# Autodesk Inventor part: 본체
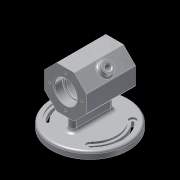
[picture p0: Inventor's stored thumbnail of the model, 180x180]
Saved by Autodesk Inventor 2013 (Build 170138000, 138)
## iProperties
Created: 2017-06
Part Number: 본체
Material: 알루미늄 6061
Document SubType Name: Modeling
Designer: Administrator
Density: 2.71 g/cm^3
Mass: 562.521 g
Surface Area: 565.55 cm^2
Volume: 207.572 cm^3
Author: Administrator
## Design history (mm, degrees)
sketch "스케치1"
  geometry: L1 (12.426, 30)-(30, 12.426); L2 (30, 12.426)-(30, -12.426); L3 (30, -12.426)-(12.426, -30); L4 (12.426, -30)-(-12.426, -30); L5 (-12.426, -30)-(-30, -12.426); L6 (-30, -12.426)-(-30, 12.426); L7 (-30, 12.426)-(-12.426, 30); L8 (-12.426, 30)-(12.426, 30); C1 r 30 at (0, 0); 2 further points
  constraints: 16 end point, 2 coincident, 1 centre point, 1 horizontal, 1 tangent, 17 other
  dimensions: "d2" = 60 diameter of C1
extrude "돌출1" new body sketch "스케치1" distance "d0" = 70; taper "d1" = 0 deg
sketch "스케치2" dims "d4" = 46
  geometry: 3 further points
  constraints: 2 vertical alignment, 1 coincident, 2 other
hole "구멍1" sketch "스케치2" at (0, 23) diameter "d6" = 3.242; stored, may be unused: countersink angle "d10" = 90 deg, drill point angle "d12" = 118 deg; dims "d7" = 8, "d8" = 4, "d9" = 2, "d11" = 10
sketch "스케치3"
  geometry: L1 (0, 0)-(70, 0); L2 (0, 0)-(0, 16); L3 (0, 16)-(12, 16); L4 (12, 16)-(12, 14); L5 (12, 14)-(15, 14); L6 (15, 14)-(15, 25); L7 (15, 25)-(55, 25); L8 (55, 25)-(55, 14); L9 (55, 14)-(58, 14); L10 (58, 14)-(58, 16); L11 (58, 16)-(70, 16); L12 (70, 16)-(70, 0); L13 (70, -12.426)-(70, 12.426) reference; 1 further point
  constraints: 24 end point, 6 parallel, 3 perpendicular, 2 collinear, 2 horizontal, 1 coincident, 1 midpoint
  dimensions: "d13" = 32 diameter of L3 L1; "d15" = 28 diameter of L5 L1; "d16" = 50 diameter of L7 L1; "d17" = 32 diameter of L11 L1; "d18" = 28 diameter of L9 L1; "d19" = 12 distance of L2.end L3.end; "d20" = 40 distance of L6.end L7.end; "d21" = 12 distance of L10.end L11.end; "d22" = 3 distance of L4.end L5.end
revolve "회전1" sketch "스케치3" stored, may be unused: angle "d23" = 90 deg
node "작업 평면1"
node "작업 평면2"
sketch "스케치4"
  geometry: L1 (12.426, 0)-(-12.426, 0) reference; L2 (-12.426, 70)-(12.426, 70) reference; L3 (0, 0)-(0, 70); C1 r 55 at (0, 35)
  constraints: 2 end point, 2 midpoint, 1 centre point
  dimensions: "d28" = 110 diameter of C1
extrude "돌출2" join sketch "스케치4" distance "d30" = 10; taper "d31" = 0 deg
sketch "스케치5"
  geometry: L1 (0, 0)-(-33.941, -33.941); L2 (0, 0)-(-33.941, 33.941); L3 (0, 0)-(-55, 0); A1 r 48 centre (0, 0) between (-33.941, 33.941) and (-33.941, -33.941); A2 r 5 centre (-30.406, -30.406) between (-33.941, -33.941) and (-26.87, -26.87); A3 r 5 centre (-30.406, 30.406) between (-26.87, 26.87) and (-33.941, 33.941); A4 r 38 centre (0, 0) between (-26.87, 26.87) and (-26.87, -26.87); 1 further point
  constraints: 9 point on circle, 6 end point, 4 centre point, 3 tangent, 2 coincident, 2 point on line, 1 horizontal, 1 horizontal alignment, 1 other
  dimensions: "d33" = 5 radius of A2; "d35" = 90 deg angle of L2 L1; "d37" = 45 deg angle of L3 L1; "d39" = 48 radius of A1
extrude "돌출3" cut sketch "스케치5" distance "d40" = 3; taper "d41" = 0 deg
sketch "스케치6"
  geometry: A1 r 48 centre (0, 0) between (-33.941, 33.941) and (-33.941, -33.941) reference; A2 r 5 centre (-30.406, -30.406) between (-33.941, -33.941) and (-26.87, -26.87) reference; A3 r 38 centre (0, 0) between (-26.87, 26.87) and (-26.87, -26.87) reference; A4 r 5 centre (-30.406, 30.406) between (-26.87, 26.87) and (-33.941, 33.941) reference; A5 r 45 centre (0, 0) between (-31.82, 31.82) and (-31.82, -31.82); A6 r 2 centre (-30.406, 30.406) between (-28.991, 28.991) and (-31.82, 31.82); A7 r 41 centre (0, 0) between (-28.991, 28.991) and (-28.991, -28.991); A8 r 2 centre (-30.406, -30.406) between (-31.82, -31.82) and (-28.991, -28.991); 1 further point
  constraints: 8 point on circle, 4 centre point, 3 other
  dimensions: "d42" = 2 radius of A6
extrude "돌출4" cut sketch "스케치6" stored distance "d44" = 3; taper "d45" = 0 deg
sketch "스케치7"
  geometry: L1 (-5, -24)-(-5, 24); L2 (5, 24)-(5, -24); A1 r 38 centre (0, 0) between (26.87, -26.87) and (26.87, 26.87) reference; A2 r 48 centre (0, 0) between (-33.941, 33.941) and (-33.941, -33.941) reference; A3 r 5 centre (0, 24) between (5, 24) and (-5, 24); A4 r 5 centre (0, -24) between (-5, -24) and (5, -24); 3 further points
  constraints: 5 point on circle, 4 end point, 3 tangent, 2 centre point, 1 horizontal alignment, 1 midpoint, 1 parallel, 1 vertical, 1 vertical alignment
  dimensions: "d46" = 5 radius of A4; "d48" = 5 radius of A3; "d49" = 48 distance of L1.start L1.end
extrude "돌출5" join sketch "스케치7" stored distance "d50" = 3; taper "d51" = 0 deg
sketch "스케치8"
  geometry: L1 (-12.426, 30)-(-30, 12.426) reference; L2 (-30, 12.426)-(-30, -12.426) reference; L3 (-30, -12.426)-(-12.426, -30) reference; L4 (-12.426, -30)-(12.426, -30) reference; L5 (12.426, -30)-(30, -12.426) reference; L6 (30, -12.426)-(30, 12.426) reference; L7 (30, 12.426)-(12.426, 30) reference; L8 (12.426, 30)-(-12.426, 30) reference; L9 (0, 0)-(0, 23); L10 (0, 0)-(26.163, 26.163); C1 r 1.621 at (23, 0) reference; C2 r 1.621 at (0, -23) reference; C3 r 1.621 at (-23, 0) reference; C4 r 16 at (0, 0) reference; C5 r 1.621 at (0, 23) reference
  constraints: 4 end point, 1 perpendicular
  dimensions: "d52" = 45 deg angle of L10 L9; "d53" = 7 distance from line of L10.end L7
node "작업 평면3"
sketch "스케치9"
  geometry: L1 (0, 12.426)-(70, 12.426) reference; C1 r 8 at (35, 0); 3 further points
  constraints: 1 centre point, 1 horizontal alignment, 1 midpoint, 1 vertical alignment
  dimensions: "d54" = 16 diameter of C1
extrude "돌출6" join sketch "스케치9" stored distance "d56" = 3; taper "d57" = 0 deg
hole "구멍2" diameter "d60" = 8; stored, may be unused: countersink angle "d64" = 90 deg, drill point angle "d66" = 0 deg; dims "d61" = 8, "d62" = 4, "d63" = 2, "d65" = 40, "d69" = 10, "d70" = 10
node "작업 평면4"
sketch "스케치10"
  geometry: L1 (0, 0)-(-17.574, 0) reference; L2 (-17.574, 0)-(-17.574, 70) reference; 2 further points
  constraints: 1 other
  dimensions: "d68" = 35 distance from line of point (12.426, 35) L1; "d71" = 30 distance from line of point (12.426, 35) L2
feature "엠보싱1" sketch "스케치10" dims "d13" = 32, "d15" = 28, "d16" = 50, "d17" = 32, "d18" = 28, "d19" = 12, "d20" = 40, "d21" = 12, "d22" = 3, "d72" = 0.5, "d73" = 0
chamfer "모따기1" distance "d74" = 1; stored, may be unused: second distance "d75" = 2, angle "d76" = 45 deg
fillet "모깎기1" dims "d77" = 3, "d78" = 1, "d81" = 5
fillet "모깎기2" dims "d79" = 0.3, "d80" = 3
node "솔리드1"
pattern_circular "원형 패턴1" dims angle "d25" = 360 deg
mirror "대칭1"
mirror "대칭2"
other parameters: "d27" = -62, "d67" = 48.75
